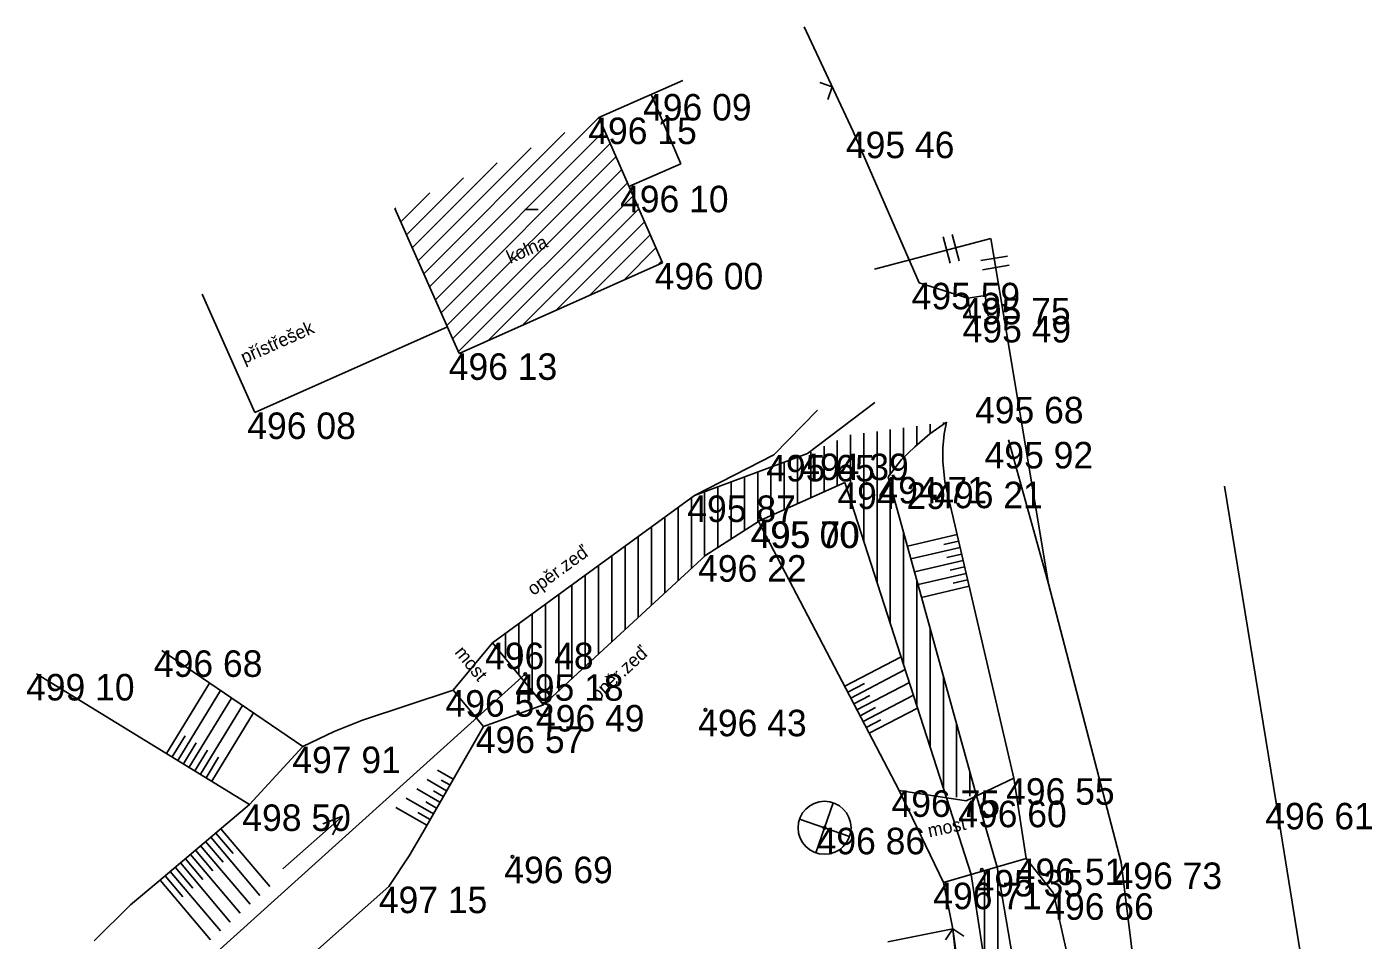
# Model space of a CAD drawing. Extents: x -554123 to -553118, y -1076825 to -1073672.
# Drawn here: x -553487.5 to -553436.8, y -1076726.2 to -1076691.7 of the extents above; entities that cross this region are included whole.
import ezdxf

# ---------------------------------------------------------------- set-up
doc = ezdxf.new("R2010")
doc.units = 0
for name, color, linetype in [('1', 7, 'Continuous'), ('12', 7, 'Continuous'), ('14', 7, 'Continuous'), ('17', 7, 'Continuous'), ('18', 7, 'Continuous'), ('26', 7, 'Continuous'), ('27', 7, 'Continuous'), ('28', 7, 'Continuous'), ('32', 7, 'Continuous'), ('34', 7, 'Continuous'), ('47', 7, 'Continuous'), ('52', 7, 'Continuous'), ('6', 7, 'Continuous'), ('62', 7, 'Continuous')]:
    doc.layers.add(name, color=color, linetype=linetype)

# ---------------------------------------------------------------- blocks, each defined once
blk = doc.blocks.new('POINT_DISPLAY')
blk.add_line((0, 0), (0, 0))
blk = doc.blocks.new('T')
at = {"layer": '6'}
blk.add_circle((0, 0), 0.05, dxfattribs=at)
blk = doc.blocks.new('STJ')
at = {"layer": '34'}
for p, q in [((-0.327, -0.945), (0.327, 0.945)), ((0.945, -0.327), (-0.945, 0.327))]:
    blk.add_line(p, q, dxfattribs=at)
for radius in [1, 0.0496]:
    blk.add_circle((0, 0), radius, dxfattribs=at)
blk = doc.blocks.new('VOTOK')
at = {"layer": '28'}
for p, q in [((-3.001, 0), (0, 0)), ((-0.75, 0.282), (0, 0)), ((0, 0), (-0.75, -0.28))]:
    blk.add_line(p, q, dxfattribs=at)
blk = doc.blocks.new('BN')
at = {"layer": '47'}
blk.add_line((-0.25, 0), (0.25, 0), dxfattribs=at)
blk = doc.blocks.new('ROV')
at = {"layer": '62'}
for p, q in [((-0.348, -0.51), (-0.348, 0.51)), ((0, -0.51), (0, 0.51))]:
    blk.add_line(p, q, dxfattribs=at)

msp = doc.modelspace()

# ---------------------------------------------------------------- linework, layer by layer
at = {"layer": '12'}
for p, q in [((-553458.18, -1076691.74), (-553456.33, -1076695.69)), ((-553457.12, -1076694.004), (-553457.59, -1076693.834)), ((-553457.12, -1076694.004), (-553457.29, -1076694.475)), ((-553456.33, -1076695.69), (-553453.84, -1076701.39)), ((-553455.03, -1076726.24), (-553452.578, -1076725.751)), ((-553452.578, -1076725.751), (-553452.856, -1076726.167)), ((-553452.578, -1076725.751), (-553452.162, -1076726.029)), ((-553452.578, -1076725.751), (-553450.54, -1076744.62))]:
    msp.add_line(p, q, dxfattribs=at)
at = {"layer": '14'}
for p, q in [((-553465.92, -1076695.16), (-553462.755, -1076693.757)), ((-553465.92, -1076695.16), (-553463.52, -1076700.64)), ((-553473.613, -1076698.585), (-553471.18, -1076704.05)), ((-553463.52, -1076700.64), (-553471.18, -1076704.05))]:
    msp.add_line(p, q, dxfattribs=at)
at = {"layer": '17'}
for p, q in [((-553452.01, -1076701.97), (-553453.84, -1076701.39)), ((-553448.97, -1076712.74), (-553450.47, -1076707.31)), ((-553440.39, -1076721), (-553442.33, -1076709.06)), ((-553446.23, -1076723.25), (-553448.97, -1076712.74)), ((-553440.39, -1076721), (-553438.01, -1076735.73)), ((-553446.23, -1076723.25), (-553443.91, -1076741.76))]:
    msp.add_line(p, q, dxfattribs=at)
at = {"layer": '18'}
for p, q in [((-553463.944, -1076694.284), (-553462.824, -1076696.904)), ((-553464.782, -1076697.757), (-553462.824, -1076696.904)), ((-553480.868, -1076701.815), (-553478.88, -1076706.28)), ((-553451.361, -1076701.867), (-553452.01, -1076701.97)), ((-553452.01, -1076701.97), (-553451.89, -1076702.73)), ((-553451.361, -1076701.867), (-553451.24, -1076702.63)), ((-553471.625, -1076703.05), (-553478.88, -1076706.28)), ((-553469.93, -1076714.96), (-553462.31, -1076709.41)), ((-553461.89, -1076711.66), (-553459.9, -1076710.39)), ((-553468, -1076717.31), (-553461.89, -1076711.66)), ((-553469.93, -1076714.96), (-553471.41, -1076716.75)), ((-553469.93, -1076714.96), (-553468, -1076717.31)), ((-553471.41, -1076716.75), (-553470.27, -1076718.12)), ((-553470.27, -1076718.12), (-553468, -1076717.31)), ((-553450.28, -1076720.07), (-553452.07, -1076720.92)), ((-553450.28, -1076720.07), (-553449.81, -1076723.1)), ((-553452.07, -1076720.92), (-553454.6, -1076720.53)), ((-553452.92, -1076724.01), (-553454.6, -1076720.53)), ((-553449.81, -1076723.1), (-553452.92, -1076724.01))]:
    msp.add_line(p, q, dxfattribs=at)
at = {"layer": '26'}
for p, q in [((-553452.416, -1076710.887), (-553454.286, -1076711.322)), ((-553452.359, -1076711.13), (-553452.917, -1076711.26)), ((-553452.302, -1076711.374), (-553454.153, -1076711.804)), ((-553452.246, -1076711.617), (-553452.798, -1076711.746)), ((-553452.189, -1076711.861), (-553454.019, -1076712.287)), ((-553452.132, -1076712.104), (-553452.678, -1076712.231)), ((-553452.076, -1076712.348), (-553453.885, -1076712.769)), ((-553452.019, -1076712.591), (-553452.559, -1076712.717)), ((-553451.963, -1076712.835), (-553453.752, -1076713.251)), ((-553456.651, -1076716.605), (-553454.525, -1076715.494)), ((-553456.42, -1076717.049), (-553454.369, -1076715.977)), ((-553482.216, -1076719.139), (-553480.588, -1076716.482)), ((-553481.789, -1076719.4), (-553480.174, -1076716.765)), ((-553456.535, -1076716.827), (-553455.909, -1076716.5)), ((-553456.188, -1076717.492), (-553454.213, -1076716.46)), ((-553481.363, -1076719.661), (-553479.761, -1076717.047)), ((-553456.304, -1076717.27), (-553455.7, -1076716.954)), ((-553455.956, -1076717.935), (-553454.057, -1076716.942)), ((-553480.937, -1076719.922), (-553479.348, -1076717.329)), ((-553480.51, -1076720.184), (-553478.934, -1076717.612)), ((-553456.072, -1076717.713), (-553455.491, -1076717.41)), ((-553455.725, -1076718.378), (-553453.901, -1076717.425)), ((-553455.841, -1076718.156), (-553455.282, -1076717.864)), ((-553482.003, -1076719.269), (-553481.516, -1076718.475)), ((-553481.576, -1076719.531), (-553481.094, -1076718.743)), ((-553481.15, -1076719.792), (-553480.671, -1076719.011)), ((-553480.724, -1076720.053), (-553480.249, -1076719.278)), ((-553471.41, -1076720.111), (-553472.002, -1076719.772)), ((-553471.658, -1076720.544), (-553472.392, -1076720.124)), ((-553471.534, -1076720.327), (-553471.863, -1076720.139)), ((-553472.155, -1076721.412), (-553473.174, -1076720.828)), ((-553471.907, -1076720.978), (-553472.783, -1076720.476)), ((-553471.783, -1076720.761), (-553472.154, -1076720.549)), ((-553472.404, -1076721.846), (-553473.566, -1076721.181)), ((-553472.031, -1076721.195), (-553472.445, -1076720.958)), ((-553472.28, -1076721.629), (-553472.737, -1076721.367)), ((-553480.547, -1076722.299), (-553478.694, -1076724.492)), ((-553480.356, -1076722.138), (-553479.705, -1076722.908)), ((-553480.165, -1076721.977), (-553478.323, -1076724.157)), ((-553481.119, -1076722.783), (-553480.462, -1076723.561)), ((-553480.929, -1076722.622), (-553479.066, -1076724.827)), ((-553480.738, -1076722.461), (-553480.084, -1076723.235)), ((-553481.692, -1076723.267), (-553479.809, -1076725.496)), ((-553481.501, -1076723.106), (-553480.841, -1076723.887)), ((-553481.31, -1076722.945), (-553479.437, -1076725.161)), ((-553482.265, -1076723.751), (-553481.599, -1076724.54)), ((-553482.074, -1076723.59), (-553480.18, -1076725.831)), ((-553481.883, -1076723.429), (-553481.22, -1076724.214)), ((-553482.456, -1076723.913), (-553480.552, -1076726.166))]:
    msp.add_line(p, q, dxfattribs=at)
at = {"layer": '27'}
for p, q in [((-553457.672, -1076706.196), (-553459.32, -1076707.88)), ((-553459.32, -1076707.88), (-553462.31, -1076709.41)), ((-553452.88, -1076708.89), (-553450.28, -1076720.07)), ((-553454.6, -1076720.53), (-553459.9, -1076710.39)), ((-553477.08, -1076718.88), (-553482.39, -1076715.25)), ((-553479.08, -1076721.06), (-553487.11, -1076716.14)), ((-553479.08, -1076721.06), (-553477.08, -1076718.88)), ((-553449.81, -1076723.1), (-553448.78, -1076724.41)), ((-553478.17, -1076728), (-553473.83, -1076724.16)), ((-553452.578, -1076725.751), (-553452.92, -1076724.01)), ((-553448.78, -1076724.41), (-553445.77, -1076737.77)), ((-553450.19, -1076742.9), (-553452.578, -1076725.751))]:
    msp.add_line(p, q, dxfattribs=at)
for points in [[(-553452.81, -1076706.64), (-553452.897, -1076707.091), (-553452.955, -1076707.626), (-553452.952, -1076708.128), (-553452.88, -1076708.89)], [(-553477.08, -1076718.88), (-553475.888, -1076718.307), (-553474.831, -1076717.887), (-553471.41, -1076716.75)], [(-553470.27, -1076718.12), (-553472.558, -1076722.115), (-553473.065, -1076722.998), (-553473.83, -1076724.16)], [(-553484.94, -1076726.2), (-553483.576, -1076724.851), (-553482.505, -1076723.954), (-553479.08, -1076721.06)]]:
    msp.add_lwpolyline(points, dxfattribs=at)
at = {"layer": '28'}
for p, q in [((-553455.51, -1076705.9), (-553458.05, -1076707.83)), ((-553458.05, -1076707.83), (-553462.31, -1076709.41)), ((-553456.65, -1076708.92), (-553459.92, -1076710.39)), ((-553456.65, -1076708.92), (-553452.808, -1076720.806)), ((-553455.01, -1076708.71), (-553451.678, -1076720.734)), ((-553481.106, -1076727.336), (-553468.69, -1076716.15)), ((-553452.808, -1076720.806), (-553451.877, -1076723.705)), ((-553450.902, -1076723.42), (-553451.678, -1076720.734)), ((-553451.877, -1076723.705), (-553449.03, -1076742.64)), ((-553447.73, -1076742.11), (-553450.902, -1076723.42))]:
    msp.add_line(p, q, dxfattribs=at)
msp.add_lwpolyline([(-553455.01, -1076708.71), (-553454.505, -1076708.059), (-553454.004, -1076707.573), (-553453.444, -1076707.086), (-553452.81, -1076706.64)], dxfattribs=at)
at = {"layer": '32'}
for p, q in [((-553472.298, -1076701.538), (-553465.92, -1076695.16)), ((-553472.516, -1076701.049), (-553467.195, -1076695.727)), ((-553472.08, -1076702.028), (-553465.705, -1076695.652)), ((-553472.734, -1076700.56), (-553468.469, -1076696.295)), ((-553471.863, -1076702.517), (-553465.489, -1076696.143)), ((-553472.952, -1076700.07), (-553469.744, -1076696.862)), ((-553471.645, -1076703.006), (-553465.274, -1076696.635)), ((-553473.17, -1076699.581), (-553471.018, -1076697.43)), ((-553471.427, -1076703.495), (-553465.059, -1076697.127)), ((-553473.387, -1076699.092), (-553472.293, -1076697.997)), ((-553471.209, -1076703.985), (-553464.843, -1076697.619)), ((-553470.076, -1076703.558), (-553464.628, -1076698.11)), ((-553473.605, -1076698.603), (-553473.567, -1076698.565)), ((-553468.801, -1076702.991), (-553464.412, -1076698.602)), ((-553467.527, -1076702.424), (-553464.197, -1076699.094)), ((-553466.252, -1076701.856), (-553463.982, -1076699.586)), ((-553464.978, -1076701.289), (-553463.766, -1076700.077)), ((-553463.704, -1076700.722), (-553463.551, -1076700.569)), ((-553456.43, -1076709.601), (-553456.43, -1076707.127)), ((-553455.93, -1076711.147), (-553455.93, -1076707.06)), ((-553455.43, -1076712.694), (-553455.43, -1076706.993)), ((-553454.93, -1076708.607), (-553454.93, -1076706.925)), ((-553454.43, -1076707.986), (-553454.43, -1076706.858)), ((-553453.93, -1076707.509), (-553453.93, -1076706.791)), ((-553453.43, -1076707.076), (-553453.43, -1076706.723)), ((-553452.93, -1076706.724), (-553452.93, -1076706.656)), ((-553457.43, -1076709.271), (-553457.43, -1076707.555)), ((-553456.93, -1076709.046), (-553456.93, -1076707.333)), ((-553458.93, -1076709.945), (-553458.93, -1076708.156)), ((-553458.43, -1076709.72), (-553458.43, -1076707.971)), ((-553457.93, -1076709.495), (-553457.93, -1076707.777)), ((-553459.93, -1076710.396), (-553459.93, -1076708.527)), ((-553459.43, -1076710.17), (-553459.43, -1076708.342)), ((-553461.43, -1076711.363), (-553461.43, -1076709.084)), ((-553460.93, -1076711.041), (-553460.93, -1076708.898)), ((-553460.43, -1076710.719), (-553460.43, -1076708.713)), ((-553454.93, -1076714.241), (-553454.93, -1076708.999)), ((-553462.43, -1076712.159), (-553462.43, -1076709.497)), ((-553461.93, -1076711.697), (-553461.93, -1076709.269)), ((-553462.93, -1076712.622), (-553462.93, -1076709.862)), ((-553463.93, -1076713.546), (-553463.93, -1076710.59)), ((-553463.43, -1076713.084), (-553463.43, -1076710.226)), ((-553464.43, -1076714.009), (-553464.43, -1076710.954)), ((-553454.43, -1076715.788), (-553454.43, -1076710.803)), ((-553465.43, -1076714.933), (-553465.43, -1076711.682)), ((-553464.93, -1076714.471), (-553464.93, -1076711.318)), ((-553465.93, -1076715.396), (-553465.93, -1076712.047)), ((-553466.43, -1076715.858), (-553466.43, -1076712.411)), ((-553453.93, -1076717.335), (-553453.93, -1076712.607)), ((-553467.43, -1076716.783), (-553467.43, -1076713.139)), ((-553466.93, -1076716.321), (-553466.93, -1076712.775)), ((-553467.93, -1076717.245), (-553467.93, -1076713.503)), ((-553468.93, -1076716.178), (-553468.93, -1076714.232)), ((-553468.43, -1076716.786), (-553468.43, -1076713.867)), ((-553469.43, -1076715.569), (-553469.43, -1076714.596)), ((-553453.43, -1076718.882), (-553453.43, -1076714.412)), ((-553452.93, -1076720.429), (-553452.93, -1076716.216)), ((-553452.43, -1076720.782), (-553452.43, -1076718.02)), ((-553451.93, -1076720.75), (-553451.93, -1076719.825)), ((-553451.377, -1076727.03), (-553451.377, -1076723.559)), ((-553450.877, -1076730.356), (-553450.877, -1076723.567))]:
    msp.add_line(p, q, dxfattribs=at)
at = {"layer": '62'}
for p, q in [((-553451.14, -1076699.72), (-553455.53, -1076700.87)), ((-553448.97, -1076712.74), (-553451.14, -1076699.72))]:
    msp.add_line(p, q, dxfattribs=at)

# ---------------------------------------------------------------- block references
at = {"layer": '1'}
for p in [(-553463.95, -1076694.27), (-553465.92, -1076695.16), (-553456.33, -1076695.69), (-553464.72, -1076697.73), (-553463.52, -1076700.64), (-553453.84, -1076701.39), (-553451.95, -1076701.96), (-553451.93, -1076702.64), (-553471.18, -1076704.05), (-553478.88, -1076706.28), (-553451.09, -1076707.39), (-553459.32, -1076707.88), (-553458.05, -1076707.83), (-553456.65, -1076708.92), (-553455.01, -1076708.71), (-553452.88, -1076708.89), (-553462.31, -1076709.41), (-553459.92, -1076710.39), (-553459.9, -1076710.39), (-553461.89, -1076711.66), (-553482.39, -1076715.25), (-553469.93, -1076714.96), (-553487.11, -1076716.14), (-553468.69, -1076716.15), (-553471.41, -1076716.75), (-553468, -1076717.31), (-553461.9, -1076717.49), (-553470.27, -1076718.12), (-553477.08, -1076718.88), (-553450.28, -1076720.07), (-553454.6, -1076720.53), (-553479.08, -1076721.06), (-553452.07, -1076720.92), (-553440.39, -1076721), (-553457.41, -1076721.94), (-553469.17, -1076723.03), (-553449.81, -1076723.1), (-553446.23, -1076723.25), (-553451.48, -1076723.53), (-553473.83, -1076724.16), (-553452.92, -1076724.01), (-553448.78, -1076724.41)]:
    msp.add_blockref('POINT_DISPLAY', p, dxfattribs=at)
at = {"layer": '28', "xscale": 1.0000004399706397, "yscale": 1.0000004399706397, "rotation": 41.333356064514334}
msp.add_blockref('VOTOK', (-553475.578, -1076721.503), dxfattribs=at)
at = {"layer": '32'}
msp.add_blockref('POINT_DISPLAY', (-553465.92, -1076695.16), dxfattribs=at)
at = {"layer": '34'}
msp.add_blockref('STJ', (-553457.41, -1076721.94), dxfattribs=at)
at = {"layer": '47'}
msp.add_blockref('BN', (-553468.457, -1076698.629), dxfattribs=at)
at = {"layer": '6'}
for p in [(-553468.69, -1076716.15), (-553461.9, -1076717.49), (-553469.17, -1076723.03), (-553451.48, -1076723.53)]:
    msp.add_blockref('T', p, dxfattribs=at)
at = {"layer": '62'}
for p, xscale, yscale, rotation in [((-553452.468, -1076700.068), 0.9999978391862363, 0.9999978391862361, 14.67934285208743), ((-553450.958, -1076700.811), 0.9999991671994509, 0.9999991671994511, -80.53776551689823)]:
    msp.add_blockref('ROV', p, dxfattribs=dict(at, xscale=xscale, yscale=yscale, rotation=rotation))

# ---------------------------------------------------------------- texts
at = {"layer": '52'}
for s, rotation, p in [('kolna', 23.9972, (-553469.26, -1076700.678)), ('přístřešek', 23.9991, (-553479.284, -1076704.456)), ('opěr.zeď', 36.0676, (-553468.387, -1076713.204)), ('most', 309.3955, (-553471.378, -1076715.338)), ('opěr.zeď', 42.76, (-553465.956, -1076717.195)), ('most', 11.6964, (-553453.462, -1076722.303))]:
    msp.add_text(s, height=0.5, rotation=rotation, dxfattribs=at).set_placement(p)
at = {"layer": '6'}
for s, p in [('496 09 ', (-553464.25, -1076695.27)), ('496 15 ', (-553466.315, -1076696.16)), ('495 46 ', (-553456.604, -1076696.69)), ('496 10 ', (-553465.117, -1076698.73)), ('496 00 ', (-553463.81, -1076701.64)), ('495 59 ', (-553454.126, -1076702.39)), ('495 75 ', (-553452.222, -1076702.96)), ('495 49 ', (-553452.204, -1076703.64)), ('496 13 ', (-553471.575, -1076705.05)), ('495 68 ', (-553451.736, -1076706.69)), ('496 08 ', (-553479.168, -1076707.28)), ('495 92 ', (-553451.376, -1076708.39)), ('495 65 ', (-553459.606, -1076708.88)), ('494 39 ', (-553458.324, -1076708.83)), ('494 29 ', (-553456.924, -1076709.92)), ('494 71 ', (-553455.377, -1076709.71)), ('496 21 ', (-553453.273, -1076709.89)), ('495 87 ', (-553462.582, -1076710.41)), ('495 00 ', (-553460.198, -1076711.39)), ('495 70 ', (-553460.174, -1076711.39)), ('496 22 ', (-553462.176, -1076712.66)), ('496 68 ', (-553482.688, -1076716.25)), ('496 48 ', (-553470.204, -1076715.96)), ('499 10 ', (-553487.507, -1076717.14)), ('495 18 ', (-553469.073, -1076717.15)), ('496 53 ', (-553471.696, -1076717.75)), ('496 49 ', (-553468.286, -1076718.31)), ('496 43 ', (-553462.174, -1076718.49)), ('496 57 ', (-553470.554, -1076719.12)), ('497 91 ', (-553477.471, -1076719.88)), ('496 55 ', (-553450.566, -1076721.07)), ('496 75 ', (-553454.884, -1076721.53)), ('498 50 ', (-553479.356, -1076722.06)), ('496 60 ', (-553452.37, -1076721.92)), ('496 61 ', (-553440.795, -1076722)), ('496 86 ', (-553457.708, -1076722.94)), ('496 69 ', (-553469.48, -1076724.03)), ('496 51 ', (-553450.203, -1076724.1)), ('496 73 ', (-553446.514, -1076724.25)), ('495 35 ', (-553451.754, -1076724.53)), ('497 15 ', (-553474.211, -1076725.16)), ('496 71 ', (-553453.311, -1076725.01)), ('496 66 ', (-553449.09, -1076725.41))]:
    msp.add_text(s, height=1, dxfattribs=at).set_placement(p)

doc.saveas('drawing.dxf')
